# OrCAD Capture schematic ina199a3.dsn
size A
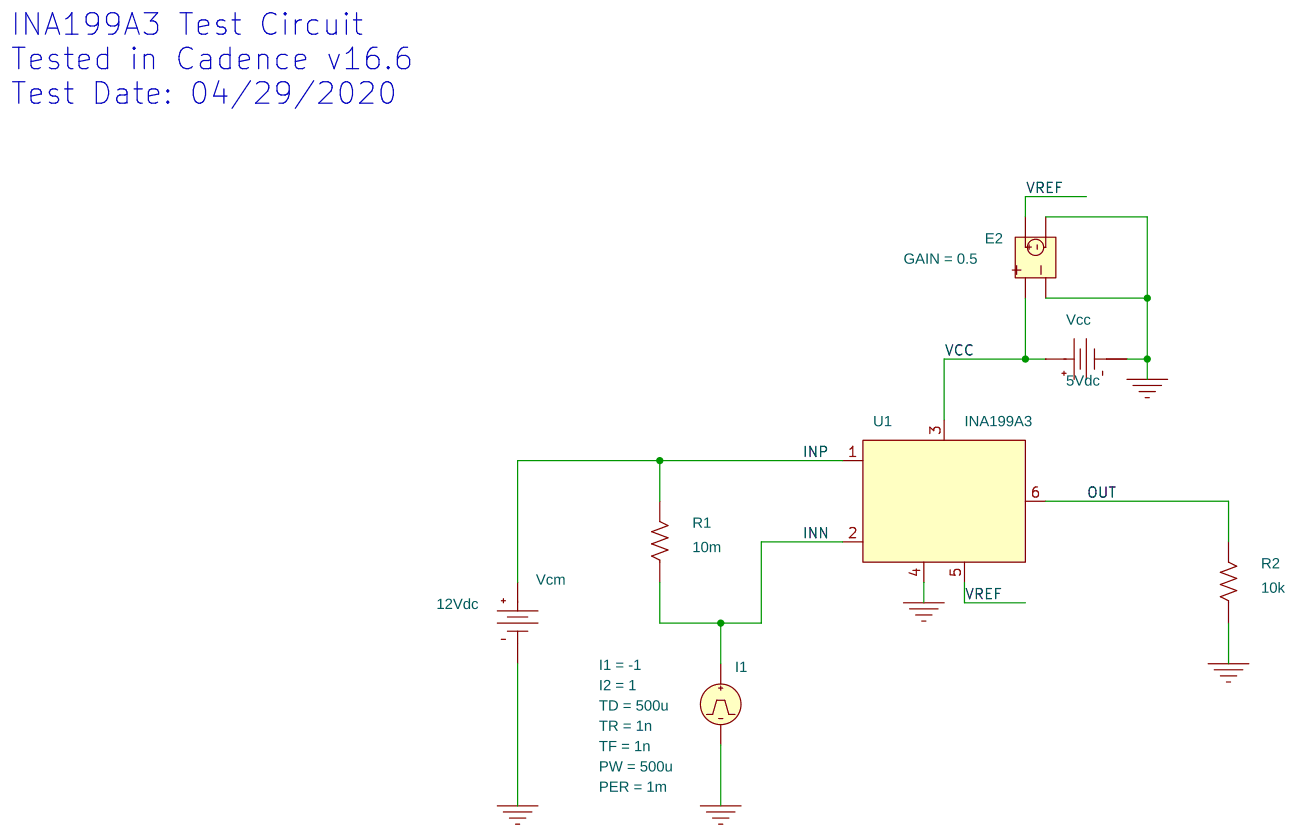
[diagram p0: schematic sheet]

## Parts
E2  E
I1  IPULSE
R1  10m  [AX/RC05]
R2  10k  [AX/RC05]
U1  INA199A3
Vcc  VDC
Vcm  VDC

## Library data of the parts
E2 = E: GAIN: 0.5
I1 = IPULSE: I1: -1; I2: 1; PER: 1m; PW: 500u; TD: 500u; TF: 1n; TR: 1n
R1 R2 = R
U1 = INA199A3
Vcc = VDC: DC: 5Vdc
Vcm = VDC: DC: 12Vdc

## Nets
VCC: E2.1 U1.3(VCC) Vcc.0(+)
0: E2.2 E2.4 I1.2(-) R2.1 U1.4(GND) Vcc.1(-) Vcm.1(-)
INN: I1.1(+) R1.1 U1.2(INN)
INP: R1.2 U1.1(INP) Vcm.0(+)
OUT: R2.2 U1.6(OUT)
VREF: E2.3 U1.5(REF)

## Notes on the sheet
- INA199A3 Test Circuit
  Tested in Cadence v16.6
  Test Date: 04/29/2020
